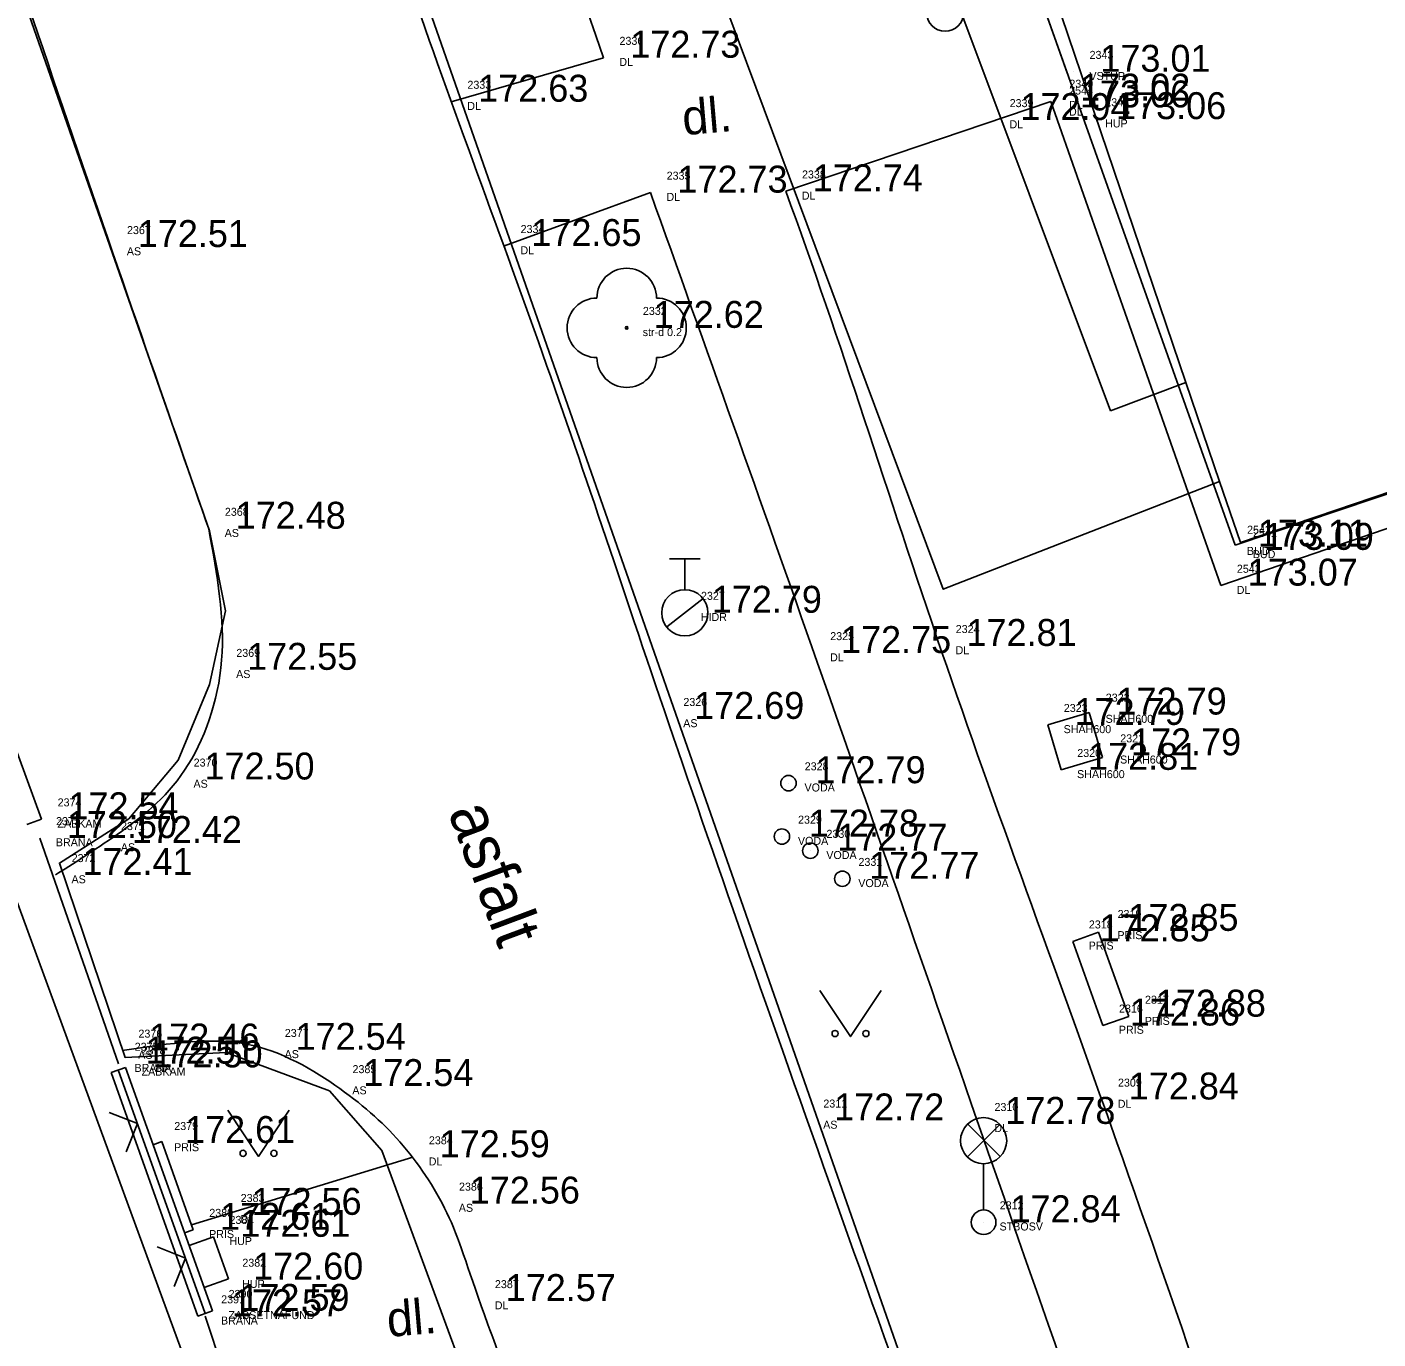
# Model space of a CAD drawing. Extents: x -566117 to -565580, y -1202428 to -1201938.
# Drawn here: x -565802.47 to -565780.52, y -1202055.22 to -1202033.91 of the extents above; entities that cross this region are included whole.
import ezdxf

# ---------------------------------------------------------------- set-up
doc = ezdxf.new("R2010")
doc.units = 0
for name, color, linetype in [('Bod', 7, 'Continuous'), ('BUDOVY_MĚŘ (Construction)', 7, 'Continuous'), ('CIZÍ_NADZEM', 7, 'Continuous'), ('Implicitní', 7, 'Continuous'), ('Kanalizace', 7, 'Continuous'), ('Katastr', 7, 'Continuous'), ('Kod', 7, 'Continuous'), ('Oplocení', 7, 'Continuous'), ('POMOC_POPIS', 7, 'Continuous'), ('Voda', 7, 'Continuous'), ('Výška', 7, 'Continuous'), ('ZELEŇ', 7, 'Continuous'), ('ZN_KULTUR', 7, 'Continuous'), ('Zpevněné plohy', 7, 'Continuous'), ('Číslo', 7, 'Continuous')]:
    doc.layers.add(name, color=color, linetype=linetype)

# ---------------------------------------------------------------- blocks, each defined once
blk = doc.blocks.new('A$C69D74C1E')
at = {"layer": 'Katastr'}
for p, q in [((263.08, 51.74), (288.17, -19.97)), ((281.29, 28.76), (280.07, 28.3)), ((281.84, 27.15), (281.29, 28.76)), ((261.89, 21.42), (280.84, -30.13))]:
    blk.add_line(p, q, dxfattribs=at)
for points in [[(280.07, 28.3), (269.53, 56.42), (289.21, 63.8), (299.75, 35.68)], [(262.97, 54.67), (263.76, 54.93), (265.7, 56.62), (277.35, 25.4), (281.84, 27.15)], [(265.69, 25.05), (265.43, 26.35), (258.33, 46.64), (257.13, 50), (256.7, 50.91), (256.13, 51.75), (255.68, 52.22)], [(281.29, 28.76), (276.19, 43.81), (288.27, 47.95), (290.04, 42.69), (288.88, 42.3), (291.25, 35.22), (292.42, 35.61), (293.22, 33.23)], [(293.7, 31.79), (294.22, 30.24), (282.18, 26.16), (281.84, 27.15)], [(264.92, 22.62), (265.43, 23.85), (265.69, 25.05)], [(267.38, 17.25), (265.7, 17.87), (264.06, 17.79), (262.99, 20.95), (264.12, 21.67), (264.92, 22.62)], [(268.46, 10.8), (269.78, 12.08), (268.23, 16.28), (267.38, 17.25)]]:
    blk.add_lwpolyline(points, dxfattribs=at)
blk = doc.blocks.new('6.560')
at = {"layer": 'CIZÍ_NADZEM'}
for p, q in [((-0.528, 2.124), (0.528, 3.18)), ((0.544, 2.13), (-0.512, 3.188)), ((0, 1.9), (0, 0.4))]:
    blk.add_line(p, q, dxfattribs=at)
for centre, radius in [((0, 2.65), 0.75), ((0, 0), 0.4)]:
    blk.add_circle(centre, radius, dxfattribs=at)
blk = doc.blocks.new('POINT_DISPLAY')
at = {"layer": 'Implicitní'}
blk.add_line((0, 0), (0, 0), dxfattribs=at)
blk = doc.blocks.new('3$13')
at = {"layer": 'ZELEŇ'}
blk.add_circle((0, 0), 0.02, dxfattribs=at)
for centre, start, end in [((0.000055, 0.484), 0, 179.9999972), ((-0.483945, 0), 90, 269.9999972), ((0.484055, 0), 270, 89.9999972), ((0.000055, -0.484), 180.0000028, 0)]:
    blk.add_arc(centre, 0.484, start, end, dxfattribs=at)
blk.add_blockref('POINT_DISPLAY', (0, 0), dxfattribs=at)
blk = doc.blocks.new('6.130')
at = {"layer": 'Voda'}
for p, q in [((-0.5, 1.75), (0.5, 1.75)), ((0, 0.75), (0, 1.75)), ((-0.588, -0.462), (0.592, 0.464))]:
    blk.add_line(p, q, dxfattribs=at)
blk.add_circle((0, 0), 0.75, dxfattribs=at)
blk = doc.blocks.new('3.140_2')
at = {"layer": 'ZN_KULTUR'}
blk.add_lwpolyline([(-1, 1.5), (0, 0), (1, 1.5)], dxfattribs=at)
for centre in [(-0.5, 0.1), (0.5, 0.1)]:
    blk.add_circle(centre, 0.1, dxfattribs=at)

msp = doc.modelspace()

# ---------------------------------------------------------------- linework, layer by layer
at = {"layer": 'BUDOVY_MĚŘ (Construction)'}
for p, q in [((-565789.151, -1202024.565), (-565782.837, -1202042.324)), ((-565782.837, -1202042.324), (-565770.705, -1202038.251))]:
    msp.add_line(p, q, dxfattribs=at)
at = {"layer": 'Implicitní'}
for p, q in [((-565786.344, -1202032.46), (-565785.559, -1202034.667)), ((-565785.883, -1202045.245), (-565785.211, -1202045.044)), ((-565784.993, -1202045.774), (-565785.211, -1202045.044)), ((-565785.664, -1202045.975), (-565785.883, -1202045.245)), ((-565785.664, -1202045.975), (-565784.993, -1202045.774)), ((-565785.476, -1202048.762), (-565785.056, -1202048.611)), ((-565784.564, -1202049.985), (-565785.056, -1202048.611)), ((-565784.987, -1202050.129), (-565785.476, -1202048.762)), ((-565784.987, -1202050.129), (-565784.564, -1202049.985)), ((-565799.795, -1202053.37), (-565796.199, -1202052.269)), ((-565799.438, -1202053.562), (-565799.833, -1202053.703)), ((-565799.195, -1202054.244), (-565799.438, -1202053.562)), ((-565799.195, -1202054.244), (-565799.589, -1202054.385))]:
    msp.add_line(p, q, dxfattribs=at)
at = {"layer": 'Kanalizace'}
msp.add_circle((-565787.549, -1202033.676), 0.3, dxfattribs=at)
at = {"layer": 'Oplocení'}
for p, q in [((-565806.822, -1202034.258), (-565802.231, -1202046.778)), ((-565802.467, -1202046.862), (-565802.232, -1202046.776)), ((-565800.98, -1202050.749), (-565802.258, -1202047.083)), ((-565801.101, -1202050.893), (-565800.866, -1202050.809)), ((-565801.101, -1202050.893), (-565799.689, -1202054.849)), ((-565800.983, -1202050.851), (-565799.571, -1202054.807)), ((-565800.866, -1202050.809), (-565799.454, -1202054.765)), ((-565800.278, -1202052.016), (-565800.417, -1202052.066)), ((-565800.278, -1202052.016), (-565799.767, -1202053.448)), ((-565799.767, -1202053.448), (-565799.906, -1202053.497)), ((-565799.689, -1202054.849), (-565799.454, -1202054.765)), ((-565799.217, -1202055.91), (-565799.574, -1202054.853))]:
    msp.add_line(p, q, dxfattribs=at)
for points in [[(-565801.132, -1202051.54), (-565800.673, -1202051.722), (-565800.855, -1202052.182)], [(-565800.351, -1202053.725), (-565799.891, -1202053.907), (-565800.074, -1202054.367)]]:
    msp.add_lwpolyline(points, dxfattribs=at)
at = {"layer": 'Voda'}
for centre in [(-565790.094, -1202046.192), (-565790.201, -1202047.059), (-565789.739, -1202047.289), (-565789.219, -1202047.745)]:
    msp.add_circle(centre, 0.125, dxfattribs=at)
at = {"layer": 'Zpevněné plohy'}
for p, q in [((-565795.573, -1202035.12), (-565793.102, -1202034.405)), ((-565790.137, -1202036.576), (-565785.831, -1202035.115)), ((-565783.071, -1202042.982), (-565785.831, -1202035.115)), ((-565794.709, -1202037.464), (-565792.337, -1202036.597)), ((-565783.071, -1202042.982), (-565770.12, -1202038.522))]:
    msp.add_line(p, q, dxfattribs=at)
for points in [[(-566046.233, -1202095.491), (-566045.931, -1202095.393), (-566043.978, -1202094.752), (-566040.389, -1202093.195), (-566035.531, -1202091.756), (-566028.975, -1202089.449), (-566022.404, -1202086.74), (-566013.877, -1202083.764), (-566006.988, -1202080.967), (-565999.231, -1202078.336), (-565993.39, -1202076.098), (-565982.391, -1202071.759), (-565967.94, -1202066.641), (-565949.498, -1202059.811), (-565935.388, -1202054.572), (-565926.049, -1202051.077), (-565917.958, -1202048.181), (-565909.827, -1202045.163), (-565898.95, -1202041.321), (-565888.732, -1202037.388), (-565879.759, -1202034.036), (-565869.081, -1202030.224), (-565859.242, -1202026.317), (-565849.297, -1202023.069), (-565843.932, -1202020.848), (-565836.631, -1202018.501), (-565830.04, -1202016.01), (-565822.89, -1202013.251), (-565816.476, -1202011.009), (-565808.989, -1202007.913), (-565802.143, -1202004.887), (-565798.059, -1202002.759), (-565793.947, -1202000.116), (-565789.34, -1201997.072), (-565785.134, -1201994.185), (-565781.539, -1201991.969), (-565778.045, -1201989.73), (-565773.319, -1201986.775), (-565768.281, -1201983.714), (-565761.544, -1201979.725), (-565754.374, -1201977.005), (-565748.201, -1201974.518), (-565743.713, -1201972.786), (-565741.115, -1201971.759), (-565739.444, -1201971.098)], [(-565765.504, -1202120.915), (-565766.654, -1202117.625), (-565769.208, -1202110.319), (-565772.995, -1202099.509), (-565775.784, -1202091.499), (-565778.608, -1202083.374), (-565780.362, -1202078.245), (-565783.417, -1202070.093), (-565785.956, -1202062.379), (-565789.304, -1202053.074), (-565792.221, -1202044.772), (-565794.036, -1202039.215), (-565796.586, -1202032.483), (-565797.905, -1202027.843), (-565799.853, -1202023.073), (-565800.495, -1202021.114), (-565801.194, -1202018.877), (-565801.765, -1202017.437), (-565802.181, -1202016.167), (-565802.282, -1202015.01), (-565801.957, -1202013.616), (-565800.562, -1202011.622), (-565797.488, -1202009.44), (-565792.081, -1202006.066), (-565785.004, -1202001.379), (-565777.423, -1201996.394), (-565770.636, -1201992.271), (-565765.226, -1201988.874), (-565760.64, -1201986.185), (-565756.42, -1201984.272), (-565751.659, -1201982.32), (-565746.843, -1201980.468), (-565743.191, -1201979), (-565741.379, -1201978.438), (-565740.291, -1201978.118), (-565738.858, -1201978.228), (-565737.215, -1201978.76), (-565736.418, -1201979.624), (-565735.993, -1201980.084)], [(-565793.102, -1202034.405), (-565794.44, -1202030.497), (-565796.33, -1202024.974), (-565798.995, -1202017.611), (-565800.243, -1202014.127), (-565800.915, -1202012.25)], [(-565799.514, -1202042.058), (-565800.047, -1202040.533), (-565801.828, -1202035.428), (-565804.345, -1202027.89), (-565806.694, -1202021.477), (-565807.727, -1202018.621), (-565807.896, -1202018.154)], [(-565792.337, -1202036.597), (-565791.447, -1202039.089), (-565789.648, -1202044.125), (-565786.826, -1202052.269), (-565783.529, -1202061.688), (-565781.105, -1202068.55), (-565779.771, -1202072.327)], [(-565790.137, -1202036.576), (-565789.243, -1202039.016), (-565787.709, -1202043.998), (-565784.789, -1202051.79), (-565781.676, -1202061.021), (-565779.214, -1202067.714), (-565777.826, -1202071.487)], [(-565802.004, -1202047.683), (-565801.735, -1202047.513), (-565801.026, -1202047.065), (-565799.821, -1202046.152), (-565799.125, -1202044.218), (-565799.377, -1202042.82), (-565799.514, -1202042.058)], [(-565782.759, -1202089.704), (-565783.58, -1202087.545), (-565785.102, -1202083.545), (-565786.694, -1202078.546), (-565787.92, -1202075.349), (-565788.516, -1202073.456), (-565789.654, -1202070.089), (-565791.743, -1202064.288), (-565793.641, -1202058.439), (-565795.172, -1202054.565), (-565795.534, -1202053.231), (-565796.327, -1202052.026), (-565797.284, -1202051.167), (-565798.852, -1202050.227), (-565800.1, -1202050.413), (-565800.918, -1202050.535)]]:
    msp.add_open_spline(points, degree=3, dxfattribs=at)

# ---------------------------------------------------------------- block references
at = {"layer": 'Bod'}
for p in [(-565793.102, -1202034.405), (-565785.465, -1202034.634), (-565795.573, -1202035.12), (-565785.796, -1202035.213), (-565785.793, -1202035.102), (-565786.764, -1202035.418), (-565785.21, -1202035.403), (-565792.337, -1202036.597), (-565790.137, -1202036.576), (-565801.105, -1202037.481), (-565794.709, -1202037.464), (-565792.723, -1202038.794), (-565799.514, -1202042.058), (-565782.906, -1202042.348), (-565782.81, -1202042.401), (-565783.071, -1202042.982), (-565791.778, -1202043.423), (-565789.678, -1202044.078), (-565787.639, -1202043.962), (-565799.328, -1202044.35), (-565792.064, -1202045.147), (-565785.202, -1202045.077), (-565785.883, -1202045.245), (-565784.966, -1202045.739), (-565785.664, -1202045.975), (-565800.022, -1202046.132), (-565790.094, -1202046.192), (-565802.231, -1202046.778), (-565802.258, -1202047.083), (-565801.201, -1202047.163), (-565790.201, -1202047.059), (-565789.739, -1202047.289), (-565802.004, -1202047.683), (-565789.219, -1202047.745), (-565785.009, -1202048.591), (-565785.476, -1202048.762), (-565784.564, -1202049.985), (-565784.987, -1202050.129), (-565800.918, -1202050.535), (-565798.54, -1202050.524), (-565800.98, -1202050.749), (-565800.866, -1202050.809), (-565797.44, -1202051.113), (-565785.003, -1202051.331), (-565789.79, -1202051.671), (-565787.01, -1202051.727), (-565800.336, -1202052.037), (-565796.199, -1202052.269), (-565795.711, -1202053.022), (-565799.257, -1202053.205), (-565799.767, -1202053.448), (-565786.924, -1202053.325), (-565799.438, -1202053.562), (-565799.231, -1202054.257), (-565795.127, -1202054.606), (-565799.454, -1202054.765), (-565799.574, -1202054.853)]:
    msp.add_blockref('POINT_DISPLAY', p, dxfattribs=at)
at = {"layer": 'CIZÍ_NADZEM', "xscale": 0.5, "yscale": 0.5}
for name, p in [('6.130', (-565791.779, -1202043.423)), ('6.560', (-565786.924, -1202053.325))]:
    msp.add_blockref(name, p, dxfattribs=at)
at = {"layer": 'Implicitní'}
msp.add_blockref('A$C69D74C1E', (-566064.93, -1202068.44), dxfattribs=at)
at = {"layer": 'ZELEŇ'}
msp.add_blockref('3$13', (-565792.723, -1202038.794), dxfattribs=at)
at = {"layer": 'ZN_KULTUR', "xscale": 0.5, "yscale": 0.5}
for p in [(-565789.087, -1202050.309), (-565798.706, -1202052.256)]:
    msp.add_blockref('3.140_2', p, dxfattribs=at)

# ---------------------------------------------------------------- texts
at = {"layer": 'Kod'}
for s, p in [('DL', (-565792.843, -1202034.539)), ('VSTUP', (-565785.205, -1202034.768)), ('DL', (-565795.314, -1202035.254)), ('DL', (-565785.537, -1202035.347)), ('DL', (-565785.534, -1202035.237)), ('DL', (-565786.504, -1202035.552)), ('HUP', (-565784.95, -1202035.538)), ('DL', (-565792.077, -1202036.731)), ('DL', (-565789.878, -1202036.711)), ('AS', (-565800.845, -1202037.615)), ('DL', (-565794.45, -1202037.598)), ('str-d 0.2', (-565792.463, -1202038.928)), ('AS', (-565799.255, -1202042.192)), ('BUD', (-565782.646, -1202042.483)), ('BUD', (-565782.55, -1202042.536)), ('DL', (-565782.812, -1202043.117)), ('HIDR', (-565791.519, -1202043.557)), ('DL', (-565789.419, -1202044.212)), ('DL', (-565787.38, -1202044.097)), ('AS', (-565799.069, -1202044.484)), ('AS', (-565791.805, -1202045.282)), ('SHAH600', (-565784.942, -1202045.211)), ('SHAH600', (-565785.624, -1202045.379)), ('SHAH600', (-565784.707, -1202045.873)), ('SHAH600', (-565785.405, -1202046.11)), ('AS', (-565799.762, -1202046.266)), ('VODA', (-565789.834, -1202046.327)), ('ZABKAM', (-565801.972, -1202046.913)), ('BRANA', (-565801.998, -1202047.217)), ('AS', (-565800.942, -1202047.298)), ('VODA', (-565789.941, -1202047.194)), ('VODA', (-565789.48, -1202047.424)), ('AS', (-565801.744, -1202047.818)), ('VODA', (-565788.96, -1202047.88)), ('PRIS', (-565784.75, -1202048.726)), ('PRIS', (-565785.217, -1202048.896)), ('PRIS', (-565784.305, -1202050.119)), ('PRIS', (-565784.727, -1202050.263)), ('AS', (-565800.659, -1202050.67)), ('AS', (-565798.281, -1202050.659)), ('BRANA', (-565800.72, -1202050.883)), ('ZABKAM', (-565800.606, -1202050.943)), ('AS', (-565797.181, -1202051.247)), ('DL', (-565784.744, -1202051.466)), ('AS', (-565789.531, -1202051.806)), ('DL', (-565786.75, -1202051.861)), ('PRIS', (-565800.077, -1202052.171)), ('DL', (-565795.94, -1202052.403)), ('AS', (-565795.451, -1202053.156)), ('DL', (-565798.998, -1202053.34)), ('PRIS', (-565799.508, -1202053.582)), ('STBOSV', (-565786.665, -1202053.459)), ('HUP', (-565799.179, -1202053.696)), ('HUP', (-565798.971, -1202054.392)), ('DL', (-565794.867, -1202054.74)), ('ZABSETNAFUND', (-565799.194, -1202054.899)), ('BRANA', (-565799.315, -1202054.987))]:
    msp.add_text(s, height=0.13, dxfattribs=at).set_placement(p)
at = {"layer": 'POMOC_POPIS'}
for s, height, rotation, p in [('dl.', 0.57, 4.9059, (-565791.798, -1202035.665)), ('asfalt', 0.75, 290.4548, (-565795.63, -1202046.658)), ('dl.', 0.57, 4.9059, (-565796.597, -1202055.19))]:
    msp.add_text(s, height=height, rotation=rotation, dxfattribs=at).set_placement(p)
at = {"layer": 'Výška'}
for s, p in [('172.73', (-565792.665, -1202034.405)), ('173.01', (-565785.027, -1202034.634)), ('172.63', (-565795.136, -1202035.12)), ('173.06', (-565785.359, -1202035.213)), ('173.02', (-565785.356, -1202035.102)), ('172.94', (-565786.326, -1202035.418)), ('173.06', (-565784.772, -1202035.403)), ('172.73', (-565791.899, -1202036.597)), ('172.74', (-565789.7, -1202036.576)), ('172.51', (-565800.667, -1202037.481)), ('172.65', (-565794.272, -1202037.464)), ('172.62', (-565792.285, -1202038.794)), ('172.48', (-565799.077, -1202042.058)), ('173.11', (-565782.468, -1202042.348)), ('173.09', (-565782.372, -1202042.401)), ('173.07', (-565782.634, -1202042.982)), ('172.79', (-565791.341, -1202043.423)), ('172.75', (-565789.241, -1202044.078)), ('172.81', (-565787.202, -1202043.962)), ('172.55', (-565798.89, -1202044.35)), ('172.69', (-565791.627, -1202045.147)), ('172.79', (-565784.764, -1202045.077)), ('172.79', (-565785.446, -1202045.245)), ('172.79', (-565784.529, -1202045.739)), ('172.81', (-565785.227, -1202045.975)), ('172.50', (-565799.584, -1202046.132)), ('172.79', (-565789.656, -1202046.192)), ('172.54', (-565801.794, -1202046.778)), ('172.50', (-565801.82, -1202047.083)), ('172.42', (-565800.764, -1202047.163)), ('172.78', (-565789.763, -1202047.059)), ('172.77', (-565789.302, -1202047.289)), ('172.41', (-565801.566, -1202047.683)), ('172.77', (-565788.782, -1202047.745)), ('172.85', (-565784.572, -1202048.591)), ('172.85', (-565785.039, -1202048.762)), ('172.88', (-565784.127, -1202049.985)), ('172.86', (-565784.549, -1202050.129)), ('172.46', (-565800.481, -1202050.535)), ('172.54', (-565798.103, -1202050.524)), ('172.51', (-565800.542, -1202050.749)), ('172.50', (-565800.428, -1202050.809)), ('172.54', (-565797.003, -1202051.113)), ('172.84', (-565784.566, -1202051.331)), ('172.72', (-565789.353, -1202051.671)), ('172.78', (-565786.572, -1202051.727)), ('172.61', (-565799.899, -1202052.037)), ('172.59', (-565795.762, -1202052.269)), ('172.56', (-565795.273, -1202053.022)), ('172.56', (-565798.82, -1202053.205)), ('172.61', (-565799.33, -1202053.448)), ('172.84', (-565786.486, -1202053.325)), ('172.61', (-565799.001, -1202053.562)), ('172.60', (-565798.793, -1202054.257)), ('172.57', (-565794.689, -1202054.606)), ('172.57', (-565799.137, -1202054.853)), ('172.59', (-565799.016, -1202054.765))]:
    msp.add_text(s, height=0.4375, dxfattribs=at).set_placement(p)
at = {"layer": 'Číslo'}
for s, p in [('2336', (-565792.84, -1202034.196)), ('2343', (-565785.202, -1202034.424)), ('2333', (-565795.311, -1202034.91)), ('2544', (-565785.534, -1202035.003)), ('2340', (-565785.531, -1202034.893)), ('2339', (-565786.501, -1202035.208)), ('2344', (-565784.947, -1202035.194)), ('2335', (-565792.074, -1202036.387)), ('2338', (-565789.875, -1202036.367)), ('2367', (-565800.842, -1202037.271)), ('2334', (-565794.447, -1202037.254)), ('2332', (-565792.46, -1202038.584)), ('2368', (-565799.252, -1202041.848)), ('2542', (-565782.643, -1202042.139)), ('2541', (-565782.547, -1202042.192)), ('2543', (-565782.809, -1202042.773)), ('2327', (-565791.516, -1202043.213)), ('2324', (-565787.377, -1202043.753)), ('2325', (-565789.416, -1202043.868)), ('2369', (-565799.066, -1202044.14)), ('2322', (-565784.939, -1202044.867)), ('2326', (-565791.802, -1202044.938)), ('2323', (-565785.621, -1202045.035)), ('2321', (-565784.704, -1202045.529)), ('2370', (-565799.759, -1202045.922)), ('2328', (-565789.831, -1202045.983)), ('2320', (-565785.402, -1202045.766)), ('2374', (-565801.969, -1202046.569)), ('2329', (-565789.939, -1202046.85)), ('2373', (-565801.995, -1202046.873)), ('2371', (-565800.939, -1202046.954)), ('2330', (-565789.477, -1202047.08)), ('2372', (-565801.741, -1202047.474)), ('2331', (-565788.957, -1202047.536)), ('2319', (-565784.747, -1202048.382)), ('2318', (-565785.214, -1202048.552)), ('2316', (-565784.724, -1202049.919)), ('2317', (-565784.302, -1202049.775)), ('2376', (-565800.656, -1202050.326)), ('2377', (-565798.278, -1202050.315)), ('2375', (-565800.717, -1202050.539)), ('2378', (-565800.603, -1202050.599)), ('2385', (-565797.178, -1202050.903)), ('2309', (-565784.741, -1202051.122)), ('2311', (-565789.528, -1202051.462)), ('2310', (-565786.747, -1202051.518)), ('2379', (-565800.074, -1202051.827)), ('2384', (-565795.937, -1202052.059)), ('2383', (-565798.995, -1202052.996)), ('2386', (-565795.448, -1202052.812)), ('2312', (-565786.662, -1202053.116)), ('2380', (-565799.505, -1202053.238)), ('2381', (-565799.176, -1202053.352)), ('2382', (-565798.968, -1202054.048)), ('2387', (-565794.864, -1202054.396)), ('2391', (-565799.312, -1202054.643)), ('2390', (-565799.191, -1202054.555))]:
    msp.add_text(s, height=0.13, dxfattribs=at).set_placement(p)

doc.saveas('drawing.dxf')
